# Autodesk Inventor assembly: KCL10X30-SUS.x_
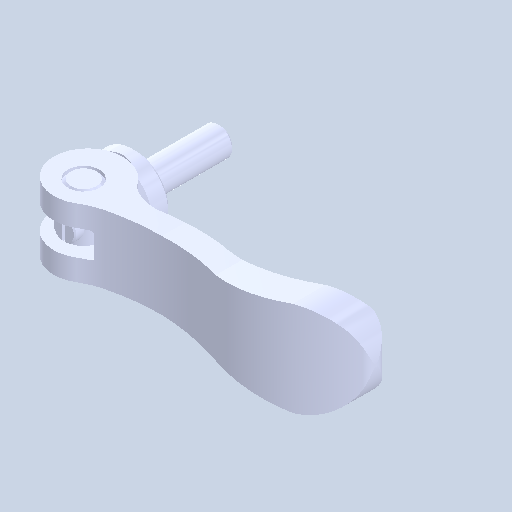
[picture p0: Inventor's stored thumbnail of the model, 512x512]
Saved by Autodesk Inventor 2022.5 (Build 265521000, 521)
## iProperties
Created: 2024-08
Part Number: KCL10X30-SUS.x_
Document SubType Name: Assembly
Designer: ImaoCorp
Author: ImaoCorp
Sending System: SOLIDWORKS 2022-2022290
MC: AMD64
MC_MODEL: Intel64 Family 6 Model 60 Stepping 3, GenuineIntel
OS: Windows_NT
FRU: Parasolid Version 33.1, build 260,  4-25-2022
FORMAT: text
GUISE: transmit
KEY: FILEKCL10X30-SUS.x_t
DATE: Thu Aug 29 10:51:02 2024
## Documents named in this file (5)
- Y:\5.更新分\2024年対応\1001_KCL\データ\kcl10x30-sus\KCL10X30-SUS.x_.iam
- Y:\5.更新分\2024年対応\1001_KCL\データ\kcl10x30-sus\KCL10X30-SUS_01.ipt
- Y:\5.更新分\2024年対応\1001_KCL\データ\kcl10x30-sus\KCL10X30-SUS_02.ipt
- Y:\5.更新分\2024年対応\1001_KCL\データ\kcl10x30-sus\KCL10X30-SUS_03.ipt
- Y:\5.更新分\2024年対応\1001_KCL\データ\kcl10x30-sus\KCL10X30-SUS_04.ipt
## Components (4 placed, 4 different names)
1. KCL10X30-SUS_01
2. KCL10X30-SUS_02
3. KCL10X30-SUS_03
4. KCL10X30-SUS_04
